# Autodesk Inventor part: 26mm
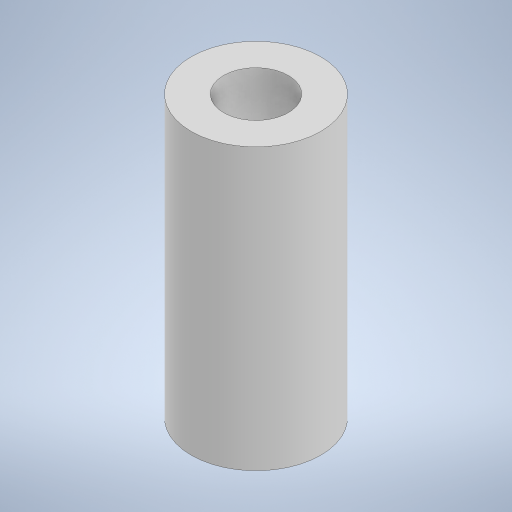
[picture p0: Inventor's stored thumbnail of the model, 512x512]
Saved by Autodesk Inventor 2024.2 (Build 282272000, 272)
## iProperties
Created: 2024-05
Part Number: 26mm
Material: Generic
Document SubType Name: Modeling
Designer: Karsten
Density: 1 g/cm^3
Appearance: Default
Author: Karsten
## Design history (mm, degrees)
sketch "Sketch1"
  geometry: C1 r 3 at (0, 0); C2 r 6 at (0, 0); 1 further point
  constraints: 2 centre point, 2 coincident
  dimensions: "d0" = 6 diameter of C1; "d1" = 12 diameter of C2
extrude "Extrusion1" new body sketch "Sketch1" distance "d2" = 26; taper "d3" = 0 deg
body "Solid1"
